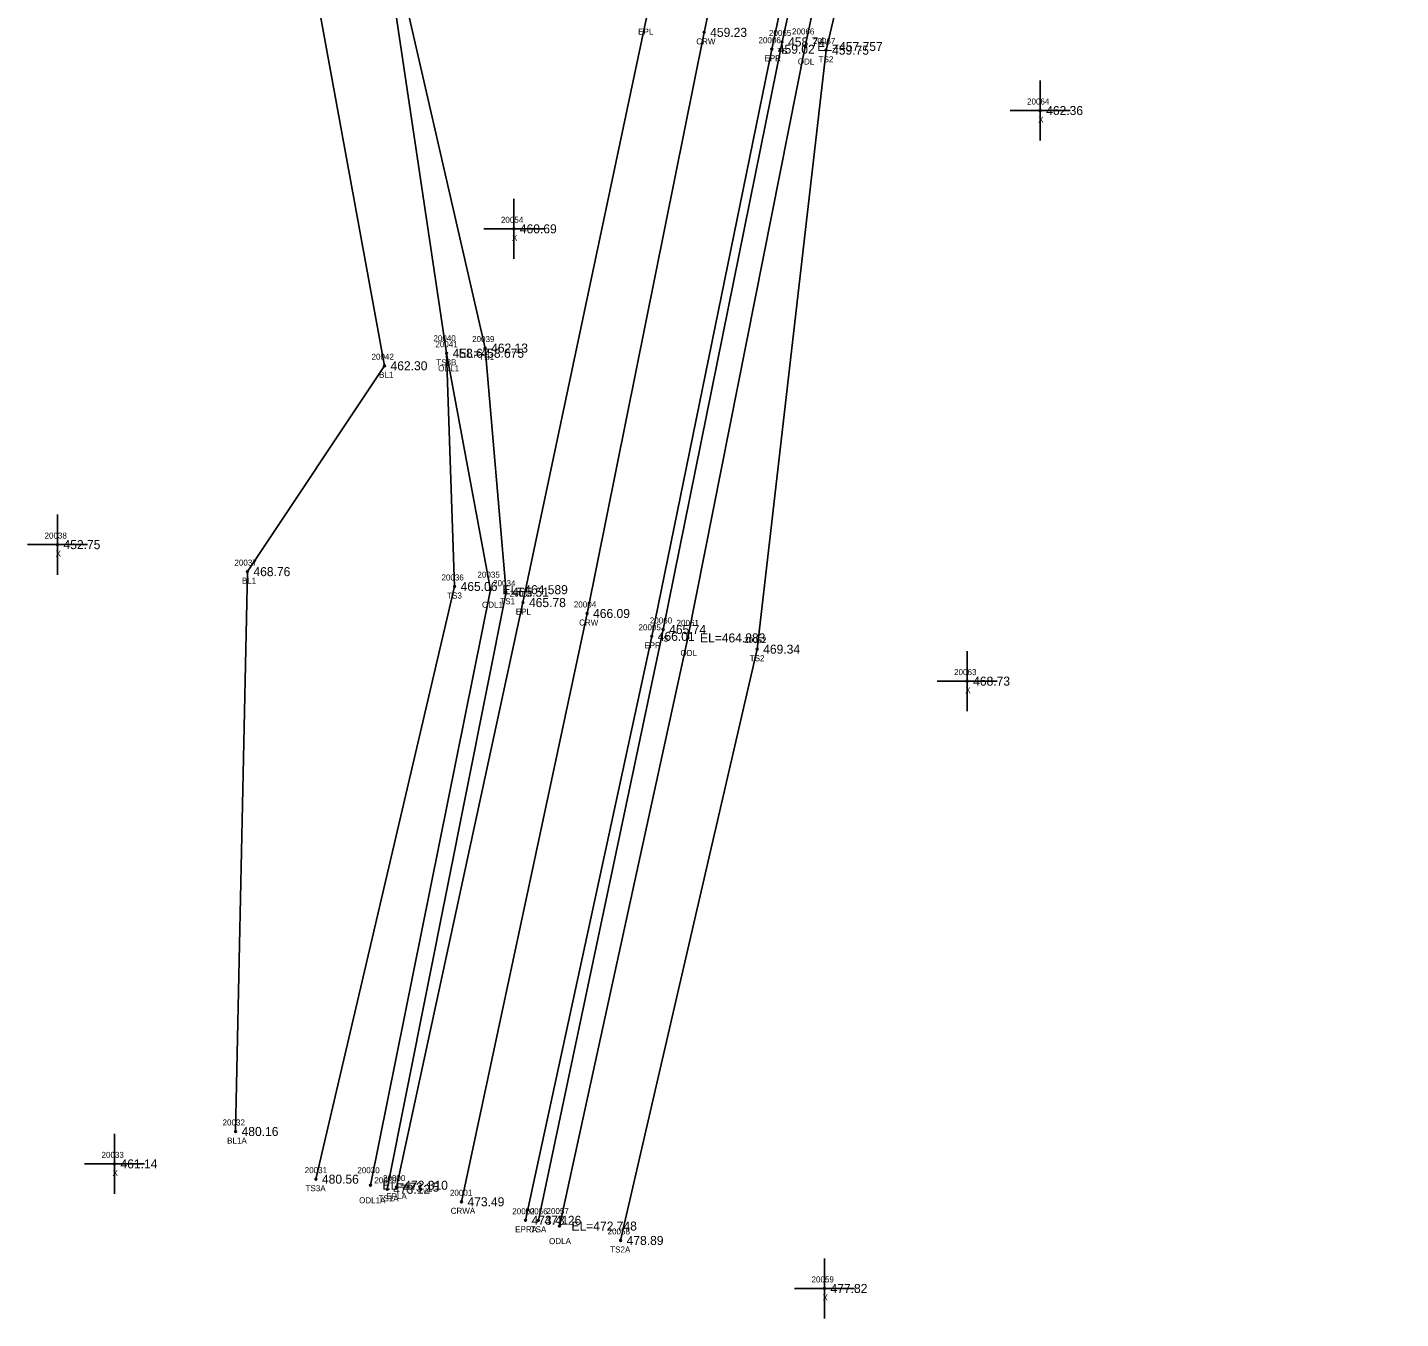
# Model space of a CAD drawing. Extents: x 1755707 to 1756750, y 975854 to 977363.
# Drawn here: x 1755973.8 to 1756202.2, y 975854 to 976068.7 of the extents above; entities that cross this region are included whole.
import ezdxf

# ---------------------------------------------------------------- set-up
doc = ezdxf.new("R2010")
doc.units = 0
for name, color, linetype in [('RD_DTM_BkLn1', 7, 'Continuous'), ('RD_DTM_BkLn2', 7, 'Continuous'), ('RD_DTM_BkLn_txCode', 7, 'Continuous'), ('RD_EX_H2O', 7, 'Continuous'), ('RD_EX_H2O_txCode', 7, 'Continuous'), ('RD_EX_Misc', 7, 'Continuous'), ('RD_EX_Misc_txCode', 7, 'Continuous'), ('RD_EX_Road', 7, 'Continuous'), ('RD_EX_Road_txCode', 7, 'Continuous'), ('RD_EX_TX_H2O_ELEV', 7, 'Continuous'), ('RD_EX_TX_Misc_ELEV', 7, 'Continuous'), ('RD_EX_TX_Road_ELEV', 7, 'Continuous'), ('RD_HC_Survey_ELEV', 7, 'Continuous'), ('RD_HC_Survey_txCode', 7, 'Continuous'), ('RD_SMD_Locator', 7, 'Continuous')]:
    doc.layers.add(name, color=color, linetype=linetype)

msp = doc.modelspace()

# ---------------------------------------------------------------- linework, layer by layer
at = {"layer": 'RD_DTM_BkLn1'}
for points in [[(1756046.01, 975873.44), (1756066.9, 975971.26), (1756086.38, 976067.89), (1756106.72, 976164.82), (1756129.4, 976267.02), (1756150.88, 976369.58), (1756171.91, 976465.4), (1756192.77, 976559.17)], [(1756008.43, 975885.13), (1756010.4, 975978.22), (1756033.21, 976012.45), (1756018.81, 976091.25), (1756027.41, 976122.36)]]:
    msp.add_lwpolyline(points, dxfattribs=at)
at = {"layer": 'RD_DTM_BkLn2'}
for points in [[(1756033.66, 975875.52), (1756053.42, 975974.8), (1756049.94, 976015.39), (1756032.6, 976091.06), (1756047.31, 976093.5), (1756074.57, 976074.24), (1756094.56, 976168.06), (1756114.78, 976271.24), (1756126.93, 976314.79), (1756122.13, 976343.84), (1756132.72, 976373.93), (1756154.73, 976470.38), (1756169.17, 976546.64), (1756175.23, 976558.93), (1756179.42, 976561.34)], [(1756058.8, 975870.36), (1756079.56, 975968.6), (1756099.34, 976066.29), (1756120.22, 976161.07), (1756142.67, 976261.19), (1756146.3, 976271.48), (1756148.91, 976276.91)], [(1756072.48, 975867.01), (1756095.2, 975965.33), (1756106.66, 976064.93), (1756129.1, 976159.98), (1756164.28, 976268.29), (1756182.56, 976252.96)], [(1756021.8, 975877.2), (1756044.86, 975975.75), (1756043.54, 976014.53)]]:
    msp.add_lwpolyline(points, dxfattribs=at)
at = {"layer": 'RD_EX_H2O'}
for points in [[(1756030.87, 975876.19), (1756050.83, 975975.22), (1756043.54, 976014.53), (1756027.41, 976122.36), (1756072.81, 976080.09), (1756091.83, 976168.45), (1756113.86, 976271.37), (1756122.13, 976343.84)], [(1756062.31, 975869.4), (1756083.69, 975967.2), (1756103.2, 976065.54), (1756123.39, 976160.48), (1756145.5, 976260.67), (1756148.22, 976268.02)]]:
    msp.add_lwpolyline(points, dxfattribs=at)
at = {"layer": 'RD_EX_Misc'}
for p, q in [((1756142.27, 976049.89), (1756142.27, 976059.89)), ((1756137.27, 976054.89), (1756147.27, 976054.89)), ((1756054.72, 976030.22), (1756054.72, 976040.22)), ((1756049.72, 976035.22), (1756059.72, 976035.22)), ((1755978.81, 975977.71), (1755978.81, 975987.71)), ((1755973.81, 975982.71), (1755983.81, 975982.71)), ((1756130.13, 975955.01), (1756130.13, 975965.01)), ((1756125.13, 975960.01), (1756135.13, 975960.01)), ((1755988.29, 975874.74), (1755988.29, 975884.74)), ((1755983.29, 975879.74), (1755993.29, 975879.74)), ((1756106.4, 975854.03), (1756106.4, 975864.03)), ((1756101.4, 975859.03), (1756111.4, 975859.03))]:
    msp.add_line(p, q, dxfattribs=at)
at = {"layer": 'RD_EX_Road'}
for points in [[(1756035.19, 975875.88), (1756056.24, 975973.07), (1756076.6, 976069.51), (1756097.1, 976167.18), (1756119.62, 976269.35), (1756142.72, 976371.31), (1756164.37, 976467.45), (1756183.15, 976561.19), (1756192.77, 976559.17)], [(1756056.66, 975870.37), (1756077.66, 975967.46), (1756097.63, 976065.09), (1756118.05, 976161.7), (1756139.04, 976265.41), (1756152.93, 976328.23), (1756161.13, 976367.36), (1756181.28, 976463.3), (1756202.22, 976557.13), (1756192.77, 976559.17)]]:
    msp.add_lwpolyline(points, dxfattribs=at)
at = {"layer": 'RD_SMD_Locator'}
for centre in [(1756086.38, 976067.89), (1756099.34, 976066.29), (1756103.2, 976065.54), (1756097.63, 976065.09), (1756106.66, 976064.93), (1756142.27, 976054.89), (1756054.72, 976035.22), (1756049.94, 976015.39), (1756043.54, 976014.53), (1756043.54, 976014.53), (1756033.21, 976012.45), (1755978.81, 975982.71), (1756010.4, 975978.22), (1756044.86, 975975.75), (1756050.83, 975975.22), (1756053.42, 975974.8), (1756056.24, 975973.07), (1756066.9, 975971.26), (1756077.66, 975967.46), (1756079.56, 975968.6), (1756083.69, 975967.2), (1756095.2, 975965.33), (1756130.13, 975960.01), (1756008.43, 975885.13), (1755988.29, 975879.74), (1756021.8, 975877.2), (1756030.87, 975876.19), (1756035.19, 975875.88), (1756033.66, 975875.52), (1756046.01, 975873.44), (1756056.66, 975870.37), (1756058.8, 975870.36), (1756062.31, 975869.4), (1756072.48, 975867.01), (1756106.4, 975859.03)]:
    msp.add_circle(centre, 0.15, dxfattribs=at)

# ---------------------------------------------------------------- texts
at = {"layer": 'RD_DTM_BkLn_txCode'}
for s, p in [('20065', (1756097.16, 976067.29)), ('20067', (1756104.48, 976065.93)), ('TS', (1756098.55, 976064.29)), ('TS2', (1756105.42, 976062.93)), ('20041', (1756041.67, 976015.53)), ('20039', (1756047.78, 976016.39)), ('20042', (1756031.05, 976013.45)), ('TS3B', (1756041.82, 976012.53)), ('TS1', (1756048.98, 976013.39)), ('BL1', (1756032.29, 976010.45)), ('20037', (1756008.24, 975979.22)), ('BL1', (1756009.48, 975976.22)), ('20036', (1756042.68, 975976.75)), ('20034', (1756051.27, 975975.8)), ('TS3', (1756043.62, 975973.75)), ('TS1', (1756052.46, 975972.8)), ('20060', (1756077.34, 975969.6)), ('TS', (1756078.77, 975966.6)), ('20062', (1756093.02, 975966.33)), ('TS2', (1756093.96, 975963.33)), ('20032', (1756006.27, 975886.13)), ('BL1A', (1756007.02, 975883.13)), ('20031', (1756019.93, 975878.2)), ('TS3A', (1756020.07, 975875.2)), ('20029', (1756031.51, 975876.52)), ('TS1A', (1756032.21, 975873.52)), ('20056', (1756056.62, 975871.36)), ('TSA', (1756057.52, 975868.36)), ('20058', (1756070.32, 975868.01)), ('TS2A', (1756070.75, 975865.01))]:
    msp.add_text(s, height=1, dxfattribs=at).set_placement(p)
at = {"layer": 'RD_EX_H2O_txCode'}
for s, p in [('20066', (1756100.99, 976067.54)), ('ODL', (1756101.95, 976062.54)), ('20040', (1756041.34, 976016.53)), ('ODL1', (1756042.13, 976011.53)), ('20035', (1756048.67, 975977.22)), ('ODL1', (1756049.42, 975972.22)), ('20061', (1756081.79, 975969.2)), ('ODL', (1756082.44, 975964.2)), ('20030', (1756028.68, 975878.19)), ('ODL1A', (1756028.98, 975873.19)), ('20057', (1756060.15, 975871.4)), ('ODLA', (1756060.58, 975866.4))]:
    msp.add_text(s, height=1, dxfattribs=at).set_placement(p)
at = {"layer": 'RD_EX_Misc_txCode'}
for s, p in [('20064', (1756140.09, 976055.89)), ('X', (1756141.95, 976052.89)), ('20054', (1756052.57, 976036.22)), ('X', (1756054.41, 976033.22)), ('20038', (1755976.65, 975983.71)), ('X', (1755978.5, 975980.71)), ('20063', (1756127.95, 975961.01)), ('X', (1756129.82, 975958.01)), ('20033', (1755986.13, 975880.74)), ('X', (1755987.97, 975877.74)), ('20059', (1756104.24, 975860.03)), ('X', (1756106.08, 975857.03))]:
    msp.add_text(s, height=1, dxfattribs=at).set_placement(p)
at = {"layer": 'RD_EX_Road_txCode'}
for s, p in [('EPL', (1756075.4, 976067.51)), ('20006', (1756095.41, 976066.09)), ('EPR', (1756096.4, 976063.09)), ('20003', (1756054.04, 975974.07)), ('EPL', (1756055.04, 975971.07)), ('20005', (1756075.46, 975968.46)), ('EPR', (1756076.43, 975965.46)), ('20000', (1756032.95, 975876.88)), ('EPLA', (1756033.49, 975873.88)), ('20002', (1756054.46, 975871.37)), ('EPRA', (1756054.94, 975868.37))]:
    msp.add_text(s, height=1, dxfattribs=at).set_placement(p)
at = {"layer": 'RD_EX_TX_H2O_ELEV'}
for s, p in [('EL=457.757', (1756105.2, 976064.79)), ('EL=458.675', (1756045.54, 976013.78)), ('EL=464.589', (1756052.83, 975974.47)), ('EL=464.883', (1756085.69, 975966.45)), ('EL=472.310', (1756032.87, 975875.44)), ('EL=472.748', (1756064.31, 975868.65))]:
    msp.add_text(s, height=1.5, dxfattribs=at).set_placement(p)
at = {"layer": 'RD_EX_TX_Misc_ELEV'}
for s, p in [('458.74', (1756100.34, 976065.54)), ('459.75', (1756107.66, 976064.18)), ('462.36', (1756143.27, 976054.14)), ('460.69', (1756055.72, 976034.47)), ('458.67', (1756044.54, 976013.78)), ('462.13', (1756050.94, 976014.64)), ('462.30', (1756034.21, 976011.7)), ('452.75', (1755979.81, 975981.96)), ('468.76', (1756011.4, 975977.47)), ('465.06', (1756045.86, 975975)), ('465.51', (1756054.42, 975974.05)), ('465.74', (1756080.56, 975967.85)), ('469.34', (1756096.2, 975964.58)), ('468.73', (1756131.13, 975959.26)), ('480.16', (1756009.43, 975884.38)), ('461.14', (1755989.29, 975878.99)), ('480.56', (1756022.8, 975876.45)), ('473.12', (1756034.66, 975874.77)), ('473.26', (1756059.8, 975869.61)), ('478.89', (1756073.48, 975866.26)), ('477.82', (1756107.4, 975858.28))]:
    msp.add_text(s, height=1.5, dxfattribs=at).set_placement(p)
at = {"layer": 'RD_EX_TX_Road_ELEV'}
for s, p in [('459.02', (1756098.63, 976064.34)), ('465.78', (1756057.24, 975972.32)), ('466.01', (1756078.66, 975966.71)), ('473.15', (1756036.19, 975875.13)), ('473.41', (1756057.66, 975869.62))]:
    msp.add_text(s, height=1.5, dxfattribs=at).set_placement(p)
at = {"layer": 'RD_HC_Survey_ELEV'}
for s, p in [('459.23', (1756087.38, 976067.14)), ('466.09', (1756067.9, 975970.51)), ('473.49', (1756047.01, 975872.69))]:
    msp.add_text(s, height=1.5, dxfattribs=at).set_placement(p)
at = {"layer": 'RD_HC_Survey_txCode'}
for s, p in [('CRW', (1756085.07, 976065.89)), ('20004', (1756064.7, 975972.26)), ('CRW', (1756065.58, 975969.26)), ('20001', (1756044.09, 975874.44)), ('CRWA', (1756044.21, 975871.44))]:
    msp.add_text(s, height=1, dxfattribs=at).set_placement(p)

doc.saveas('drawing.dxf')
